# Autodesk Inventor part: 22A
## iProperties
Created: 2011-12
Part Number: 22A
Document SubType Name: Modeling
Designer: D Cole
Density: 1 g/cm^3
Author: D Cole
Translation Standard: STEP AP214IS
File Name: P:\Fastrack\53972_CRANE 3D\Press Fit\HATTERSLEY\100TH-PF\22MM\22A.stp
Preprocessor: Autodesk Inventor 2008
Postprocessor: Build: 342, Release: 2008 SP3 - Date: Tue 05/27/2008
Sent Units: MILLIMETERS
Uncertainty: 0.01
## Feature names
1. Base1
